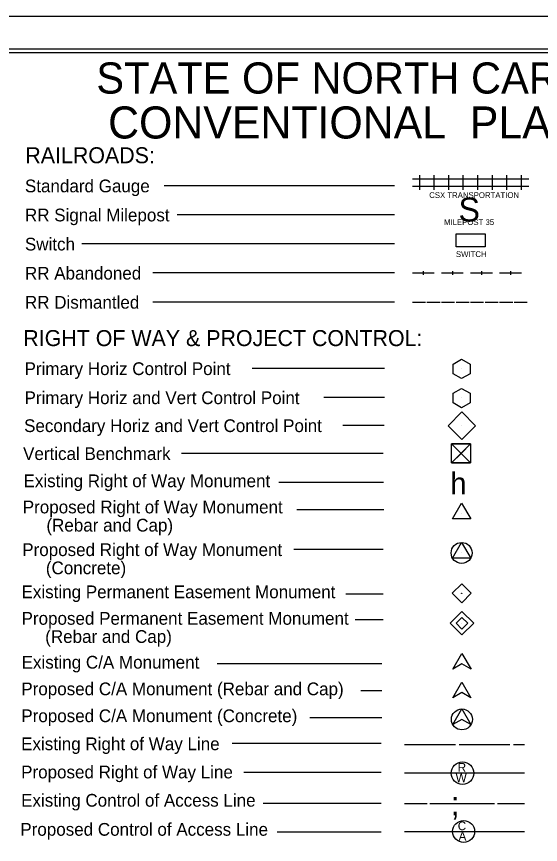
# Model space of a CAD drawing. Extents: x 2041685 to 2043369, y 619046 to 620146.
# Drawn here: x 2042248 to 2042608, y 619576 to 620146 of the extents above; entities that cross this region are included whole.
import ezdxf

# ---------------------------------------------------------------- set-up
doc = ezdxf.new("R2010")
doc.units = 0
for name, color, linetype in [('Default', 7, 'Continuous'), ('Prop ROW Permanent Easement CELL', 7, 'Continuous'), ('Sheet Cutting Line CELL', 7, 'Continuous'), ('Sheet Plot Border Inside CELL', 7, 'Continuous'), ('Sheet Plot Border Outside CELL', 7, 'Continuous'), ('Sheet Symbology CELL', 7, 'Continuous')]:
    doc.layers.add(name, color=color, linetype=linetype)

msp = doc.modelspace()

# ---------------------------------------------------------------- linework, layer by layer
at = {"layer": 'Default'}
for p, q in [((2042553.9, 619903.31), (2042553.9, 619903.31)), ((2042553.89, 619883.35), (2042553.89, 619883.35)), ((2042554.02, 619864.27), (2042554.02, 619864.27)), ((2042553.52, 619845.27), (2042553.52, 619845.27)), ((2042553.99, 619749.05), (2042553.99, 619749.05))]:
    msp.add_line(p, q, dxfattribs=at)
for points in [[(2042553.9, 619896.66), (2042548.1, 619899.95), (2042548.1, 619906.61), (2042553.9, 619909.97), (2042559.69, 619906.67), (2042559.69, 619899.95), (2042553.9, 619896.66)], [(2042559.99, 619851.75), (2042547.03, 619838.78), (2042553.51, 619845.26), (2042559.99, 619838.78), (2042547.03, 619851.75)], [(2042553.51, 619845.26), (2042559.99, 619851.75), (2042547.03, 619851.75), (2042553.51, 619845.26)], [(2042553.51, 619845.26), (2042547.03, 619838.78), (2042559.99, 619838.78), (2042553.51, 619845.26)]]:
    msp.add_lwpolyline(points, dxfattribs=at)
for points in [[(2042548.06, 619886.72), (2042553.92, 619889.99), (2042559.78, 619886.77), (2042559.69, 619880.05), (2042553.83, 619876.64), (2042548.06, 619879.91)], [(2042544.61, 619864.3), (2042554.07, 619873.76), (2042563.54, 619864.29), (2042554.09, 619854.83)], [(2042547.03, 619851.75), (2042559.99, 619851.75), (2042559.99, 619838.78), (2042547.03, 619838.78)], [(2042547.49, 619749.05), (2042553.99, 619755.55), (2042560.48, 619749.05), (2042553.99, 619742.56)]]:
    msp.add_lwpolyline(points, close=True, dxfattribs=at)
msp.add_circle((2042553.99, 619749.05), 0.126, dxfattribs=at)
at = {"layer": 'Prop ROW Permanent Easement CELL'}
msp.add_line((2042554.16, 619728.45), (2042554.16, 619728.45), dxfattribs=at)
for points in [[(2042554.16, 619736.5), (2042562.22, 619728.44), (2042554.16, 619720.39), (2042546.11, 619728.44)], [(2042554.16, 619732.47), (2042558.19, 619728.44), (2042554.16, 619724.42), (2042550.14, 619728.44)]]:
    msp.add_lwpolyline(points, close=True, dxfattribs=at)
at = {"layer": 'Sheet Cutting Line CELL'}
msp.add_line((2043369.03, 620145.62), (2041685.03, 620145.62), dxfattribs=at)
at = {"layer": 'Sheet Plot Border Inside CELL'}
msp.add_lwpolyline([(2041698.03, 619068.07), (2043364.53, 619068.07), (2043364.53, 620123.17), (2041698.03, 620123.17)], close=True, dxfattribs=at)
at = {"layer": 'Sheet Plot Border Outside CELL'}
msp.add_lwpolyline([(2041685.03, 619045.62), (2043369.03, 619045.62), (2043369.03, 620145.62), (2041685.03, 620145.62)], close=True, dxfattribs=at)
at = {"layer": 'Sheet Symbology CELL'}
for p, q in [((2042520.05, 620034.07), (2042530.05, 620034.07)), ((2042525.05, 620026.57), (2042525.05, 620036.57)), ((2042530.05, 620034.07), (2042540.05, 620034.07)), ((2042535.05, 620026.57), (2042535.05, 620036.57)), ((2042540.05, 620034.07), (2042550.05, 620034.07)), ((2042545.05, 620026.57), (2042545.05, 620036.57)), ((2042550.05, 620034.07), (2042560.05, 620034.07)), ((2042555.05, 620026.57), (2042555.05, 620036.57)), ((2042560.05, 620034.07), (2042570.05, 620034.07)), ((2042565.05, 620026.57), (2042565.05, 620036.57)), ((2042570.05, 620034.07), (2042580.05, 620034.07)), ((2042575.05, 620026.57), (2042575.05, 620036.57)), ((2042580.05, 620034.07), (2042590.05, 620034.07)), ((2042585.05, 620026.57), (2042585.05, 620036.57)), ((2042590.05, 620034.07), (2042600.05, 620034.07)), ((2042595.05, 620026.57), (2042595.05, 620036.57)), ((2042507.66, 620029.31), (2042349.24, 620029.31)), ((2042520.05, 620029.07), (2042530.05, 620029.07)), ((2042530.05, 620029.07), (2042540.05, 620029.07)), ((2042540.05, 620029.07), (2042550.05, 620029.07)), ((2042550.05, 620029.07), (2042560.05, 620029.07)), ((2042560.05, 620029.07), (2042570.05, 620029.07)), ((2042570.05, 620029.07), (2042580.05, 620029.07)), ((2042580.05, 620029.07), (2042590.05, 620029.07)), ((2042590.05, 620029.07), (2042600.05, 620029.07)), ((2042507.66, 620009.31), (2042358.11, 620009.31)), ((2042507.66, 619989.31), (2042292.74, 619989.31)), ((2042507.66, 619969.31), (2042341.49, 619969.31)), ((2042520.05, 619969.31), (2042535.05, 619969.31)), ((2042527.55, 619970.56), (2042527.55, 619968.06)), ((2042540.05, 619969.31), (2042555.05, 619969.31)), ((2042547.55, 619970.56), (2042547.55, 619968.06)), ((2042560.05, 619969.31), (2042575.05, 619969.31)), ((2042567.55, 619970.56), (2042567.55, 619968.06)), ((2042580.05, 619969.31), (2042595.05, 619969.31)), ((2042587.55, 619970.56), (2042587.55, 619968.06)), ((2042507.66, 619949.31), (2042341.49, 619949.31)), ((2042507.66, 619949.31), (2042341.49, 619949.31)), ((2042520.05, 619949.31), (2042529.05, 619949.31)), ((2042530.05, 619949.31), (2042539.05, 619949.31)), ((2042540.05, 619949.31), (2042549.05, 619949.31)), ((2042550.05, 619949.31), (2042559.05, 619949.31)), ((2042560.05, 619949.31), (2042569.05, 619949.31)), ((2042570.05, 619949.31), (2042579.05, 619949.31)), ((2042580.05, 619949.31), (2042589.05, 619949.31)), ((2042590.05, 619949.31), (2042599.05, 619949.31)), ((2042500.96, 619903.68), (2042409.93, 619903.68)), ((2042500.96, 619883.68), (2042459.05, 619883.68)), ((2042500.65, 619864.48), (2042472.1, 619864.48)), ((2042499.96, 619845.26), (2042361.12, 619845.26)), ((2042500.27, 619825.28), (2042428.22, 619825.28)), ((2042500.37, 619806.49), (2042440.64, 619806.49)), ((2042553.89, 619803.88), (2042553.89, 619803.88)), ((2042499.87, 619779.09), (2042438.38, 619779.09)), ((2042553.91, 619776.82), (2042553.91, 619776.82)), ((2042499.95, 619748.39), (2042474.16, 619748.39)), ((2042499.95, 619730.77), (2042480.67, 619730.77)), ((2042547.9, 619696.87), (2042554.15, 619707.67)), ((2042554.15, 619707.67), (2042560.4, 619696.87)), ((2042498.96, 619700.56), (2042385.72, 619700.56)), ((2042554.15, 619700.47), (2042547.9, 619696.87)), ((2042560.4, 619696.87), (2042554.15, 619700.47)), ((2042547.86, 619677.26), (2042554.11, 619688.06)), ((2042554.11, 619688.06), (2042560.36, 619677.26)), ((2042499.06, 619682.02), (2042484.49, 619682.02)), ((2042554.11, 619680.86), (2042547.86, 619677.26)), ((2042560.36, 619677.26), (2042554.11, 619680.86)), ((2042547.86, 619658.75), (2042554.11, 619669.55)), ((2042554.11, 619669.55), (2042560.36, 619658.75)), ((2042499.06, 619663.52), (2042449.39, 619663.52)), ((2042554.11, 619662.35), (2042547.86, 619658.75)), ((2042560.36, 619658.75), (2042554.11, 619662.35)), ((2042498.62, 619645.74), (2042396.1, 619645.74)), ((2042514.65, 619645.16), (2042549.65, 619645.16)), ((2042552.15, 619645.16), (2042587.15, 619645.16)), ((2042589.65, 619645.16), (2042597.15, 619645.16)), ((2042498.62, 619625.74), (2042404.09, 619625.74)), ((2042514.65, 619625.61), (2042597.15, 619625.61)), ((2042498.62, 619604.61), (2042417.3, 619604.61)), ((2042514.65, 619604.61), (2042530.11, 619604.61)), ((2042532.11, 619604.61), (2042576.52, 619604.61)), ((2042578.52, 619604.61), (2042597.15, 619604.61)), ((2042498.62, 619584.79), (2042426.97, 619584.79)), ((2042514.65, 619585.18), (2042597.15, 619585.18))]:
    msp.add_line(p, q, dxfattribs=at)
for points in [[(2043352.03, 620120.62), (2041852.03, 620120.62), (2041852.03, 619071.63), (2043352.03, 619071.63)], [(2042550.05, 619996.27), (2042570.05, 619996.27), (2042570.05, 619987.17), (2042550.05, 619987.17)], [(2042547.64, 619800.28), (2042553.89, 619811.08), (2042560.14, 619800.28)], [(2042547.66, 619773.22), (2042553.91, 619784.02), (2042560.16, 619773.22)]]:
    msp.add_lwpolyline(points, close=True, dxfattribs=at)
for centre, radius in [((2042553.9, 619776.81), 7.2), ((2042554.11, 619662.35), 7.2), ((2042554.5, 619625.41), 7.75), ((2042555.29, 619585.28), 7.58)]:
    msp.add_circle(centre, radius, dxfattribs=at)

# ---------------------------------------------------------------- texts
for s, height, p in [('STATE OF NORTH CAROLINA, DIVISION OF HIGHWAYS', 21.419, (2042302.59, 620092.66)), ('CONVENTIONAL  PLAN SHEET SYMBOLS', 22.0323, (2042310.72, 620061.78)), ('RAILROADS:', 11, (2042253.77, 620044.76)), ('Standard Gauge', 8.75, (2042253.49, 620024.78)), ('S', 16.5, (2042551.81, 620004.68)), ('RR Signal Milepost', 8.75, (2042253.49, 620004.78)), ('Switch', 8.75, (2042253.49, 619984.78)), ('RR Abandoned', 8.75, (2042253.49, 619964.78)), ('RR Dismantled', 8.75, (2042253.49, 619944.78)), ('RIGHT OF WAY & PROJECT CONTROL:', 11, (2042252.36, 619919.03)), ('Primary Horiz Control Point', 8.75, (2042253.21, 619899.13)), ('Primary Horiz and Vert Control Point', 8.75, (2042253.21, 619879.13)), ('Secondary Horiz and Vert Control Point', 8.75, (2042252.9, 619859.93)), ('Vertical Benchmark', 8.75, (2042252.21, 619840.71)), ('h', 15, (2042546.12, 619817.1)), ('Existing Right of Way Monument', 8.75, (2042252.52, 619822)), ('Proposed Right of Way Monument', 8.75, (2042252, 619804.02)), ('     (Rebar and Cap)', 8.75, (2042252, 619791.52)), ('Proposed Right of Way Monument', 8.75, (2042251.63, 619774.67)), ('     (Concrete)', 8.75, (2042251.63, 619762.17)), ('Existing Permanent Easement Monument', 8.75, (2042251.15, 619745.68)), ('Proposed Permanent Easement Monument', 8.75, (2042251.18, 619727.45)), ('     (Rebar and Cap)', 8.75, (2042251.18, 619714.95)), ('Existing C/A Monument', 8.75, (2042251.21, 619697.28)), ('Proposed C/A Monument (Rebar and Cap)', 8.75, (2042251, 619678.97)), ('Proposed C/A Monument (Concrete)', 8.75, (2042251, 619660.46)), ('Existing Right of Way Line', 8.75, (2042250.87, 619641.19)), ('Proposed Right of Way Line', 8.75, (2042250.87, 619621.81)), ('R', 6.08, (2042551.16, 619626.32)), ('W', 6.08, (2042549.78, 619619.16)), ('Existing Control of Access Line', 8.75, (2042250.87, 619602.35)), (';', 16.5, (2042546.44, 619596.43)), ('Proposed Control of Access Line', 8.75, (2042250.32, 619582.37)), ('C', 5.94, (2042551.27, 619586.17)), ('A', 5.94, (2042551.86, 619579.04))]:
    msp.add_text(s, height=height, dxfattribs=at).set_placement(p)
for s, p in [('CSX TRANSPORTATION', (2042531.61, 620020.83)), ('MILEPOST 35', (2042541.8, 620002.26)), ('SWITCH', (2042550, 619980.26))]:
    msp.add_text(s, height=4, rotation=360, dxfattribs=at).set_placement(p)

doc.saveas('drawing.dxf')
